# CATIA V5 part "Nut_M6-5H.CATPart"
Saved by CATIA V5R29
Part number: Nut_M6-5H
Source: Unknown
Bounding box of the stored display mesh (mm): x -5 to 5, y -5.774 to 5.774, z -2.5 to 2.5
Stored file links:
  C:\Users\Administrator\Desktop\프로젝트\Boxfold\TapeCutter\Nut_M6-5H.CATPart
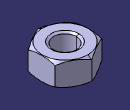
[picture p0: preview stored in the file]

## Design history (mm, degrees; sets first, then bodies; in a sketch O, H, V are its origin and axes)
Body1 (main body)
  Solid1 "PartBody": solid without history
